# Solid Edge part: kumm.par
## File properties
Author: Romil
Template: iso part.par
Last saved by: Romil
Revision: 54
Application: Solid Edge
Accuracy: 0.990
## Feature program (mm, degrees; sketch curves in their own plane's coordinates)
sketch for "unnamed RevolvedProtrusion 1" plane through (0, 0, 0) normal (0, -1, 0) x-axis (1, 0, 0)
  bspline degree 3 poles (-9.4, 20.2938) (-9.4087, 21.8618) (-8.8539, 22.8813) (-7.7358, 23.3525) knots 0 1 multiplicities 4 4
  arc centre (8.5983, 20.3869) radius 2.2356 from (9.748, 22.3041) to (9.4, 18.3) cw
  line (9.4, 18.3) -> (9.4, 13.5)
  arc centre (9.5, 13.5) radius 0.1 from (9.4, 13.5) to (9.5, 13.4) ccw
  line (11.8, 13.4) -> (9.5, 13.4)
  arc centre (11.8, 13.5) radius 0.1 from (11.8, 13.4) to (11.9, 13.5) ccw
  line (11.9, 14.8) -> (11.9, 13.5)
  arc centre (12, 14.8) radius 0.1 from (12, 14.9) to (11.9, 14.8) ccw
  line (13, 14.9) -> (12, 14.9)
  arc centre (13, 15) radius 0.1 from (13.0805, 14.9406) to (13, 14.9) cw
  arc centre (13.2414, 14.8218) radius 0.2 from (13.2066, 15.0188) to (13.0805, 14.9406) ccw
  line (14.3086, 15.2131) -> (13.2066, 15.0188)
  arc centre (14.2738, 15.4101) radius 0.2 from (14.3086, 15.2131) to (14.427, 15.2815) ccw
  line (14.427, 15.2815) -> (14.9532, 15.9086)
  arc centre (14.8, 16.0371) radius 0.2 from (15, 16.0371) to (14.9532, 15.9086) cw
  line (15, 18.2909) -> (15, 16.0371)
  line (15, 20.1432) -> (15, 18.2909)
  line (15, 21.6816) -> (15, 20.1432)
  arc centre (14.8, 21.6816) radius 0.2 from (14.9181, 21.843) to (15, 21.6816) cw
  line (11.34, 24.4614) -> (14.9181, 21.843)
  arc centre (11.2219, 24.3) radius 0.2 from (11.2219, 24.5) to (11.34, 24.4614) cw
  line (11.2219, 24.5) -> (8.2, 24.5)
  arc centre (8.2, 24.7) radius 0.2 from (8, 24.7) to (8.2, 24.5) ccw
  line (8, 24.7) -> (8, 26.4683)
  arc centre (7.8, 26.4683) radius 0.2 from (8, 26.4683) to (7.8552, 26.6605) ccw
  line (3.2171, 27.9922) -> (7.8552, 26.6605)
  arc centre (3.1619, 27.8) radius 0.2 from (3.1619, 28) to (3.2171, 27.9922) cw
  line (-3.1619, 28) -> (3.1619, 28)
  arc centre (-3.1619, 27.8) radius 0.2 from (-3.1619, 28) to (-3.2171, 27.9922) ccw
  line (-3.2171, 27.9922) -> (-7.8552, 26.6605)
  arc centre (-7.8, 26.4683) radius 0.2 from (-8, 26.4683) to (-7.8552, 26.6605) cw
  line (-8, 24.7) -> (-8, 26.4683)
  arc centre (-8.2, 24.7) radius 0.2 from (-8, 24.7) to (-8.2, 24.5) cw
  line (-11.2219, 24.5) -> (-8.2, 24.5)
  arc centre (-11.2219, 24.3) radius 0.2 from (-11.2219, 24.5) to (-11.34, 24.4614) ccw
  line (-11.34, 24.4614) -> (-14.9181, 21.843)
  arc centre (-14.8, 21.6816) radius 0.2 from (-14.9181, 21.843) to (-15, 21.6816) ccw
  line (-15, 21.6816) -> (-15, 20.1432)
  line (-15, 20.1432) -> (-15, 17.5371)
  arc centre (-14.8, 17.5371) radius 0.2 from (-15, 17.5371) to (-14.9532, 17.4086) ccw
  line (-13.9346, 16.1947) -> (-14.9532, 17.4086)
  arc centre (-13.7814, 16.3232) radius 0.2 from (-13.8162, 16.1263) to (-13.9346, 16.1947) cw
  line (-13.2066, 16.0188) -> (-13.8162, 16.1263)
  arc centre (-13.2414, 15.8218) radius 0.2 from (-13.0805, 15.9406) to (-13.2066, 16.0188) ccw
  arc centre (-13, 16) radius 0.1 from (-13, 15.9) to (-13.0805, 15.9406) cw
  line (-12, 15.9) -> (-13, 15.9)
  arc centre (-12, 15.8) radius 0.1 from (-11.9, 15.8) to (-12, 15.9) ccw
  line (-11.9, 15.8) -> (-11.9, 15)
  arc centre (-11.8, 15) radius 0.1 from (-11.9, 15) to (-11.8, 14.9) ccw
  line (-9.5, 14.9) -> (-11.8, 14.9)
  arc centre (-9.5, 15) radius 0.1 from (-9.5, 14.9) to (-9.4, 15) ccw
  line (-9.4, 18.3) -> (-9.4, 15)
  line (-9.4, 18.3) -> (-9.4, 20.2938)
revolve "unnamed RevolvedProtrusion 1" add full turn 360 deg
sketch for "unnamed RevolvedCutout 1" plane through (-8, 0, 26.6189) normal (0, -1, 0) x-axis (1, 0, 0)
revolve "unnamed RevolvedCutout 1" cut finite
sketch for "RevolvedCutout_22" plane through (0, 0, 0) normal (0, -1, 0) x-axis (1, 0, 0)
revolve "RevolvedCutout_22" cut finite 11.25 deg
pattern "unnamed Pattern 1" of "RevolvedCutout_22", "unnamed RevolvedCutout 1"
revolve "unnamed RevolvedCutout 2" cut finite 11.25 deg
revolve "unnamed RevolvedCutout 3" cut finite 11.25 deg
revolve "unnamed RevolvedCutout 4" cut finite 11.25 deg
revolve "unnamed RevolvedCutout 5" cut finite 11.25 deg
revolve "unnamed RevolvedCutout 6" cut finite 11.25 deg
revolve "unnamed RevolvedCutout 7" cut finite 11.25 deg
revolve "unnamed RevolvedCutout 8" cut finite 11.25 deg
revolve "unnamed RevolvedCutout 9" cut finite 11.25 deg
revolve "unnamed RevolvedCutout 10" cut finite 11.25 deg
revolve "unnamed RevolvedCutout 11" cut finite 11.25 deg
revolve "unnamed RevolvedCutout 12" cut finite 11.25 deg
revolve "unnamed RevolvedCutout 13" cut finite 11.25 deg
revolve "unnamed RevolvedCutout 14" cut finite 11.25 deg
revolve "unnamed RevolvedCutout 15" cut finite 11.25 deg
revolve "unnamed RevolvedCutout 16" cut finite 11.25 deg
revolve "unnamed RevolvedCutout 17" cut finite 11.25 deg
revolve "unnamed RevolvedCutout 18" cut finite 11.25 deg
revolve "unnamed RevolvedCutout 19" cut finite 11.25 deg
revolve "unnamed RevolvedCutout 20" cut finite 11.25 deg
revolve "unnamed RevolvedCutout 21" cut finite 11.25 deg
revolve "unnamed RevolvedCutout 22" cut finite 11.25 deg
revolve "unnamed RevolvedCutout 23" cut finite 11.25 deg
revolve "unnamed RevolvedCutout 24" cut finite 11.25 deg
revolve "unnamed RevolvedCutout 25" cut finite 11.25 deg
revolve "unnamed RevolvedCutout 26" cut finite 11.25 deg
revolve "unnamed RevolvedCutout 27" cut finite 11.25 deg
revolve "unnamed RevolvedCutout 28" cut finite 11.25 deg
revolve "unnamed RevolvedCutout 29" cut finite 11.25 deg
revolve "unnamed RevolvedCutout 30" cut finite 11.25 deg
revolve "unnamed RevolvedCutout 31" cut finite 11.25 deg
sketch used by "ExtrudedProtrusion_7" plane through (15, 0, 0) normal (1, 0, 0) x-axis (0, 1, 0)
extrude "ExtrudedProtrusion_7" add finite 0.25 along +normal
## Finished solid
Body 1: solid body, 700 faces, 1918 edges, 1236 vertices.
  Faces by surface: plane 248, torus 210, cone 132, cylinder 69, swept 40, spun 1
  Edges by curve: circle 960, line 878, spline 80
Bounding box of the edges (mm; curved faces can reach further): 30.250 x 56.000 x 56.000, from (-15, -28, -28) to (15.25, 28, 28).
Cylindrical faces by radius (mm): R13.4 x1, R14.9 x2, R15.9 x1, R24.5 x32, R25.8811 x32, R28 x1
Conical faces (half-angle, radius in mm at the cone's reference point): 10 deg R15.0188 x1, 10 deg R16.1263 x1, 16.02 deg R25.8733 x32, 16.02 deg R26.6605 x16, 16.02 deg R27.9922 x16, 21.0099 deg R24.4969 x16, 21.2128 deg R24.4967 x16, 36.1962 deg R21.843 x16, 36.1962 deg R24.4614 x16, 50 deg R15.2815 x1, 50 deg R17.4086 x1
Toroidal faces (ring radius, tube radius in mm): R6.0492 r18.9538 x1, R13.5 r0.1 x2, R14.8 r0.1 x1, R14.8218 r0.2 x1, R15 r0.1 x3, R15.4101 r0.2 x1, R15.8 r0.1 x1, R15.8218 r0.2 x1, R16 r0.1 x1, R16.0371 r0.2 x1, R16.3232 r0.2 x1, R17.5371 r0.2 x1, R20.3869 r2.2356 x1, R21.6816 r0.2 x2, R24.3 r0.2 x32, R24.3102 r0.2 x16, R24.3103 r0.2 x16, R24.7 r0.2 x32, R25.6811 r0.2 x32, R26.4683 r0.2 x32, R27.8 r0.2 x32
Planar faces by outward normal: +x 59, +y 2, +z 2, -x 35, -y 2, -z 2, oblique 146
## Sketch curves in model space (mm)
spline (15, 18.0681, 4.7565) -> (15, 18.2634, 4.0886) -> (15, 18.8808, 3.8909)
spline (15, 19.1298, 4.9927) -> (15, 18.599, 4.8746) -> (15, 18.0681, 4.7565)
spline (15, 18.8808, 3.8909) -> (15, 19.2486, 4.3549) -> (15, 19.1298, 4.9927)
spline (15, 18.0396, 3.9091) -> (15, 17.5384, 3.2705) -> (15, 17.0371, 2.6319)
spline (15, 19.371, 5.4417) -> (15, 19.4708, 3.8189) -> (15, 18.0396, 3.9091)
spline (15, 16.5515, 4.8144) -> (15, 17.9612, 5.128) -> (15, 19.371, 5.4417)
spline (15, 16.6353, 4.4377) -> (15, 16.5934, 4.626) -> (15, 16.5515, 4.8144)
spline (15, 17.7542, 4.6867) -> (15, 17.1948, 4.5622) -> (15, 16.6353, 4.4377)
spline (15, 17.8491, 4.2601) -> (15, 17.8017, 4.4734) -> (15, 17.7542, 4.6867)
spline (15, 16.9286, 3.1194) -> (15, 17.3889, 3.6897) -> (15, 17.8491, 4.2601)
spline (15, 17.0371, 2.6319) -> (15, 16.9829, 2.8756) -> (15, 16.9286, 3.1194)
closed spline through (15, 15.8399, 8.049), (15, 17.1389, 8.6471), (15, 17.1754, 9.621), (15, 15.8759, 9.1431), (15, 15.515, 8.1142)
closed spline through (15, 16.8517, 8.0196), (15, 15.0388, 8.2433), (15, 16.2381, 9.7782), (15, 17.8156, 9.391)
spline (15, 14.9314, 11.6444) -> (15, 15.6253, 11.2834) -> (15, 15.7727, 11.9988)
spline (15, 14.6744, 11.4542) -> (15, 14.8029, 11.5493) -> (15, 14.9314, 11.6444)
spline (15, 13.6328, 11.3799) -> (15, 14.4145, 10.3846) -> (15, 14.6744, 11.4542)
spline (15, 13.617, 11.4012) -> (15, 13.6249, 11.3906) -> (15, 13.6328, 11.3799)
spline (15, 13.2886, 11.1581) -> (15, 13.4528, 11.2797) -> (15, 13.617, 11.4012)
spline (15, 15.1556, 11.0902) -> (15, 14.2867, 10.0027) -> (15, 13.2886, 11.1581)
spline (15, 15.1769, 11.106) -> (15, 15.1662, 11.0981) -> (15, 15.1556, 11.0902)
spline (15, 15.4676, 12.6719) -> (15, 16.2918, 11.5316) -> (15, 15.1769, 11.106)
spline (15, 15.1391, 12.4288) -> (15, 15.3034, 12.5504) -> (15, 15.4676, 12.6719)
spline (15, 15.1526, 12.4106) -> (15, 15.1459, 12.4197) -> (15, 15.1391, 12.4288)
spline (15, 15.7727, 11.9988) -> (15, 15.4951, 12.2507) -> (15, 15.1526, 12.4106)
spline (15, 12.9842, 12.892) -> (15, 12.8612, 12.24) -> (15, 12.7382, 11.5881)
spline (15, 14.2725, 13.1195) -> (15, 13.6283, 13.0057) -> (15, 12.9842, 12.892)
spline (15, 13.9812, 13.4114) -> (15, 14.1268, 13.2654) -> (15, 14.2725, 13.1195)
spline (15, 13.0273, 13.2236) -> (15, 13.5042, 13.3175) -> (15, 13.9812, 13.4114)
spline (15, 13.2275, 14.1664) -> (15, 13.1274, 13.695) -> (15, 13.0273, 13.2236)
spline (15, 12.9108, 14.4837) -> (15, 13.0691, 14.3251) -> (15, 13.2275, 14.1664)
spline (15, 12.6634, 13.1785) -> (15, 12.7871, 13.8311) -> (15, 12.9108, 14.4837)
spline (15, 11.3765, 12.9523) -> (15, 12.02, 13.0654) -> (15, 12.6634, 13.1785)
spline (15, 11.6678, 12.6605) -> (15, 11.5222, 12.8064) -> (15, 11.3765, 12.9523)
spline (15, 12.6203, 12.8468) -> (15, 12.1441, 12.7536) -> (15, 11.6678, 12.6605)
spline (15, 12.4215, 11.9054) -> (15, 12.5209, 12.3761) -> (15, 12.6203, 12.8468)
spline (15, 12.7382, 11.5881) -> (15, 12.5799, 11.7467) -> (15, 12.4215, 11.9054)
spline (15, 10.5236, 15.3082) -> (15, 10.2144, 14.1863) -> (15, 11.1266, 14.3087)
spline (15, 11.1266, 14.3087) -> (15, 11.1801, 14.9939) -> (15, 10.5236, 15.3082)
spline (15, 10.6894, 15.5314) -> (15, 11.5556, 15.0595) -> (15, 11.4515, 14.0863)
spline (15, 12.1899, 15.5242) -> (15, 11.4502, 15.9701) -> (15, 10.6894, 15.5314)
spline (15, 12.205, 15.5129) -> (15, 12.1975, 15.5186) -> (15, 12.1899, 15.5242)
spline (15, 12.4261, 15.8105) -> (15, 12.3156, 15.6617) -> (15, 12.205, 15.5129)
spline (15, 11.4515, 14.0863) -> (15, 9.9588, 15.1895) -> (15, 12.4261, 15.8105)
spline (15, 8.4205, 17.0178) -> (15, 9.1249, 16.516) -> (15, 9.1032, 15.6829)
spline (15, 8.7841, 17.705) -> (15, 8.6023, 17.3614) -> (15, 8.4205, 17.0178)
spline (15, 9.8525, 17.1397) -> (15, 9.3183, 17.4223) -> (15, 8.7841, 17.705)
spline (15, 10.0082, 17.434) -> (15, 9.9304, 17.2869) -> (15, 9.8525, 17.1397)
spline (15, 8.6088, 18.1744) -> (15, 9.3085, 17.8042) -> (15, 10.0082, 17.434)
spline (15, 7.9161, 16.8652) -> (15, 8.2624, 17.5198) -> (15, 8.6088, 18.1744)
spline (15, 7.4158, 16.1177) -> (15, 8.7068, 15.7846) -> (15, 7.9161, 16.8652)
spline (15, 7.3923, 16.1301) -> (15, 7.4041, 16.1239) -> (15, 7.4158, 16.1177)
spline (15, 7.2013, 15.769) -> (15, 7.2968, 15.9495) -> (15, 7.3923, 16.1301)
spline (15, 9.1032, 15.6829) -> (15, 8.1564, 15.1501) -> (15, 7.2013, 15.769)
spline (15, 3.3554, 17.2898) -> (15, 4.1147, 17.0781) -> (15, 4.5596, 17.7276)
spline (15, 3.6335, 18.4914) -> (15, 3.4945, 17.8906) -> (15, 3.3554, 17.2898)
spline (15, 4.5596, 17.7276) -> (15, 4.4521, 18.5079) -> (15, 3.6335, 18.4914)
spline (15, 3.7026, 18.7899) -> (15, 4.7046, 18.7864) -> (15, 4.9338, 17.6837)
spline (15, 3.7542, 19.0129) -> (15, 3.7284, 18.9014) -> (15, 3.7026, 18.7899)
spline (15, 3.3966, 19.0956) -> (15, 3.5754, 19.0543) -> (15, 3.7542, 19.0129)
spline (15, 2.7271, 16.2023) -> (15, 3.0619, 17.649) -> (15, 3.3966, 19.0956)
spline (15, 3.0846, 16.1196) -> (15, 2.9059, 16.1609) -> (15, 2.7271, 16.2023)
spline (15, 3.2889, 17.0023) -> (15, 3.1868, 16.5609) -> (15, 3.0846, 16.1196)
spline (15, 4.9338, 17.6837) -> (15, 4.3041, 16.7859) -> (15, 3.2889, 17.0023)
spline (15, 2.0928, 19.2683) -> (15, 2.0134, 18.1873) -> (15, 1.934, 17.1063)
spline (15, 1.7268, 19.2951) -> (15, 1.9098, 19.2817) -> (15, 2.0928, 19.2683)
spline (15, 1.6082, 17.6803) -> (15, 1.6675, 18.4877) -> (15, 1.7268, 19.2951)
spline (15, 0.7609, 19.3661) -> (15, 0.6619, 17.9745) -> (15, 1.6082, 17.6803)
spline (15, 0.3949, 19.3929) -> (15, 0.5779, 19.3795) -> (15, 0.7609, 19.3661)
spline (15, 1.5856, 17.3728) -> (15, 0.2978, 17.7066) -> (15, 0.3949, 19.3929)
spline (15, 1.568, 17.1332) -> (15, 1.5768, 17.253) -> (15, 1.5856, 17.3728)
spline (15, 1.934, 17.1063) -> (15, 1.751, 17.1198) -> (15, 1.568, 17.1332)
closed spline through (15, -1.034, 18.2597), (15, -1.6899, 19.0346), (15, -2.2133, 18.1758), (15, -1.5596, 17.3922)
closed spline through (15, -0.6607, 18.2896), (15, -1.5377, 17.0733), (15, -2.5848, 18.1472), (15, -1.7084, 19.3557)
spline (15, -3.584, 19.0311) -> (15, -3.5427, 18.8407) -> (15, -3.5014, 18.6503)
spline (15, -4.2744, 18.5641) -> (15, -3.9121, 18.9349) -> (15, -3.584, 19.0311)
spline (15, -4.3425, 18.8783) -> (15, -4.3084, 18.7212) -> (15, -4.2744, 18.5641)
spline (15, -4.7011, 18.8006) -> (15, -4.5218, 18.8395) -> (15, -4.3425, 18.8783)
spline (15, -4.2419, 16.682) -> (15, -4.4715, 17.7413) -> (15, -4.7011, 18.8006)
spline (15, -3.8833, 16.7598) -> (15, -4.0626, 16.7209) -> (15, -4.2419, 16.682)
spline (15, -4.2082, 18.259) -> (15, -4.0458, 17.5094) -> (15, -3.8833, 16.7598)
spline (15, -3.5199, 18.6463) -> (15, -3.8694, 18.5708) -> (15, -4.2082, 18.259)
spline (15, -3.5014, 18.6503) -> (15, -3.5107, 18.6483) -> (15, -3.5199, 18.6463)
spline (15, -5.2033, 16.6211) -> (15, -5.5845, 16.2913) -> (15, -6.0158, 16.0512)
spline (15, -5.6463, 17.8004) -> (15, -5.4248, 17.2107) -> (15, -5.2033, 16.6211)
spline (15, -6.6273, 17.4319) -> (15, -6.1368, 17.6162) -> (15, -5.6463, 17.8004)
spline (15, -6.5076, 17.1132) -> (15, -6.5675, 17.2726) -> (15, -6.6273, 17.4319)
spline (15, -5.8896, 17.3453) -> (15, -6.1986, 17.2293) -> (15, -6.5076, 17.1132)
spline (15, -5.6289, 16.6512) -> (15, -5.7592, 16.9983) -> (15, -5.8896, 17.3453)
spline (15, -5.9609, 18.5087) -> (15, -7.5014, 17.2481) -> (15, -5.6289, 16.6512)
spline (15, -5.9307, 18.52) -> (15, -5.9458, 18.5144) -> (15, -5.9609, 18.5087)
spline (15, -6.0944, 18.9556) -> (15, -6.0126, 18.7378) -> (15, -5.9307, 18.52)
spline (15, -6.0158, 16.0512) -> (15, -7.9577, 17.5522) -> (15, -6.0944, 18.9556)
closed spline through (15, -10.6506, 15.3206), (15, -12.114, 15.6808), (15, -11.8626, 14.0424), (15, -10.4635, 14.0392)
closed spline through (15, -11.2787, 16.2423), (15, -9.9499, 14.7334), (15, -11.1755, 13.3194), (15, -12.685, 14.5882), (15, -11.7671, 16.2326)
spline (15, -12.1226, 12.5051) -> (15, -12.3146, 12.0394) -> (15, -12.592, 11.6307)
spline (15, -13.0487, 13.3592) -> (15, -12.5856, 12.9321) -> (15, -12.1226, 12.5051)
spline (15, -13.7592, 12.5889) -> (15, -13.4039, 12.974) -> (15, -13.0487, 13.3592)
spline (15, -13.5089, 12.358) -> (15, -13.634, 12.4735) -> (15, -13.7592, 12.5889)
spline (15, -13.0613, 12.8433) -> (15, -13.2851, 12.6007) -> (15, -13.5089, 12.358)
spline (15, -12.5162, 12.3406) -> (15, -12.7888, 12.5919) -> (15, -13.0613, 12.8433)
spline (15, -13.6494, 13.849) -> (15, -14.4562, 12.0305) -> (15, -12.5162, 12.3406)
spline (15, -13.6263, 13.874) -> (15, -13.6379, 13.8615) -> (15, -13.6494, 13.849)
spline (15, -13.9684, 14.1895) -> (15, -13.7974, 14.0317) -> (15, -13.6263, 13.874)
spline (15, -12.592, 11.6307) -> (15, -15.0015, 12.0973) -> (15, -13.9684, 14.1895)
spline (15, -13.9449, 10.1058) -> (15, -14.4399, 9.3491) -> (15, -14.9349, 8.5925)
spline (15, -14.2298, 10.2922) -> (15, -14.0874, 10.199) -> (15, -13.9449, 10.1058)
spline (15, -15.0086, 9.1018) -> (15, -14.6192, 9.697) -> (15, -14.2298, 10.2922)
spline (15, -15.9061, 9.6889) -> (15, -15.4573, 9.3954) -> (15, -15.0086, 9.1018)
spline (15, -15.1823, 10.7954) -> (15, -15.5442, 10.2422) -> (15, -15.9061, 9.6889)
spline (15, -15.4672, 10.9818) -> (15, -15.3247, 10.8886) -> (15, -15.1823, 10.7954)
spline (15, -16.191, 9.8753) -> (15, -15.8291, 10.4286) -> (15, -15.4672, 10.9818)
spline (15, -16.8559, 10.3103) -> (15, -16.5235, 10.0928) -> (15, -16.191, 9.8753)
spline (15, -16.0772, 11.5006) -> (15, -16.4665, 10.9054) -> (15, -16.8559, 10.3103)
spline (15, -16.3621, 11.687) -> (15, -16.2196, 11.5938) -> (15, -16.0772, 11.5006)
spline (15, -17.3521, 10.1737) -> (15, -16.8571, 10.9304) -> (15, -16.3621, 11.687)
spline (15, -14.9349, 8.5925) -> (15, -16.1435, 9.3831) -> (15, -17.3521, 10.1737)
spline (15, -15.6028, 8.0596) -> (15, -15.4481, 7.9885) -> (15, -15.2934, 7.9175)
spline (15, -16.1402, 6.8889) -> (15, -15.8715, 7.4742) -> (15, -15.6028, 8.0596)
spline (15, -18.4559, 7.9519) -> (15, -17.2981, 7.4204) -> (15, -16.1402, 6.8889)
spline (15, -18.6169, 7.6012) -> (15, -18.5364, 7.7765) -> (15, -18.4559, 7.9519)
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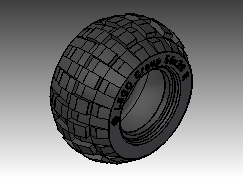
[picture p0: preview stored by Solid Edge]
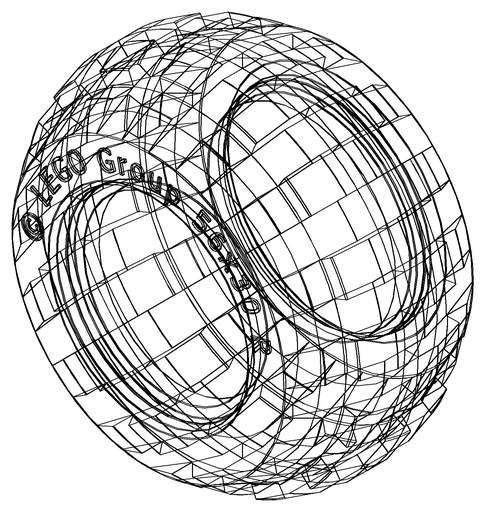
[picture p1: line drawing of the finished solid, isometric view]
